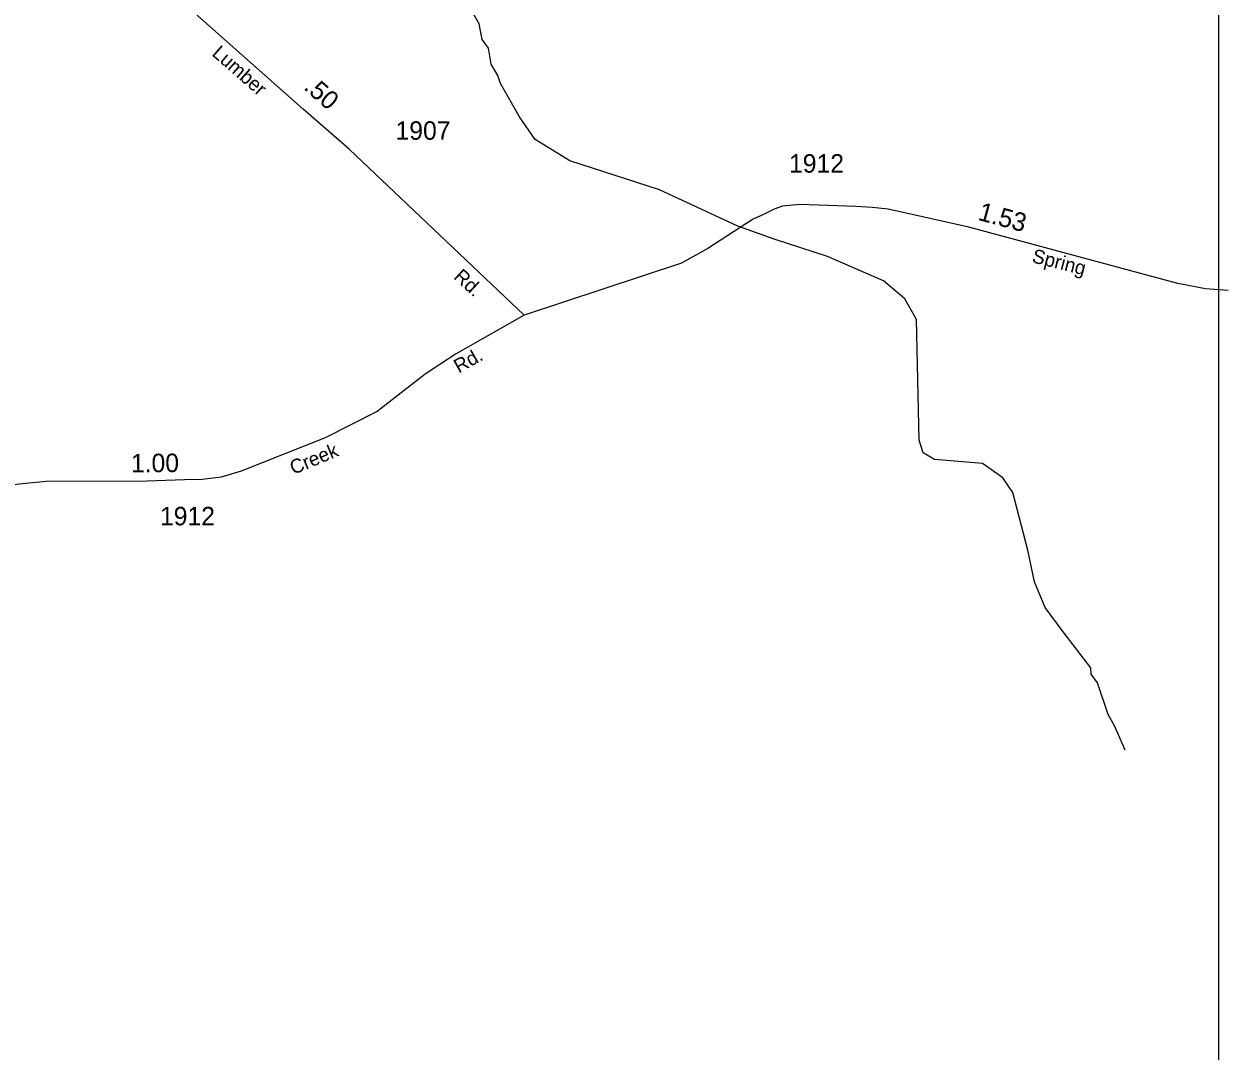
# Model space of a CAD drawing. Extents: x 2532689 to 2764727, y 536648 to 732970.
# Drawn here: x 2687851 to 2695958, y 575256 to 582198 of the extents above; entities that cross this region are included whole.
import ezdxf

# ---------------------------------------------------------------- set-up
doc = ezdxf.new("R2010")
doc.units = 0
for name, color, linetype in [('Exist Hydrographic Creek Single Shore', 7, 'Continuous'), ('Exist Road Secondary Mileage Hundredths English Label', 7, 'Continuous'), ('Exist Road Secondary Type 51 Attributed', 7, 'Continuous'), ('Exist Road Secondary Type 51 Label', 7, 'Continuous'), ('Exist Road Secondary Type 51 Number Label', 7, 'Continuous'), ('Map Preparation Inset Cut Line', 7, 'Continuous')]:
    doc.layers.add(name, color=color, linetype=linetype)

msp = doc.modelspace()

# ---------------------------------------------------------------- linework, layer by layer
at = {"layer": 'Exist Hydrographic Creek Single Shore'}
for points in [[(2692527.2, 580902.1), (2692147.5, 581077.1), (2691542.4, 581272.6), (2691306.3, 581417.4), (2691202.4, 581570.8), (2691072.4, 581795.4), (2691054.3, 581850.5), (2691010.4, 581927.6), (2690991.4, 582035.1), (2690948.5, 582092.5), (2690929.5, 582200.1), (2690868.3, 582306), (2690850.5, 582370.9), (2690753.3, 582593.6)], [(2695295.4, 577290), (2695259.5, 577374), (2695224.5, 577454.7), (2695181.4, 577531.7), (2695109.4, 577745.5), (2695066.4, 577802.9), (2695065.4, 577845.5), (2694876.5, 578090.7), (2694755.5, 578253.3), (2694684.4, 578427.8), (2694638.4, 578642.6), (2694537.3, 579032.5), (2694468.4, 579131.6), (2694332.5, 579227.9), (2694007.5, 579254.2), (2693931.4, 579300.4), (2693904.3, 579384.6), (2693885.5, 580201.4), (2693806.3, 580339.5), (2693662.4, 580461.7), (2693283.5, 580627), (2692922.4, 580743.8), (2692678.3, 580832.5), (2692527.2, 580902.1)]]:
    msp.add_lwpolyline(points, dxfattribs=at)
at = {"layer": 'Exist Road Secondary Type 51 Attributed'}
for points in [[(2691231.8, 580229.9), (2690048.7, 581351.9), (2689738.3, 581622.7), (2688926.2, 582341.6)], [(2695993.4, 580397.4), (2695839.5, 580407.8), (2695653.1, 580443.3), (2694238.6, 580825.8), (2693694.1, 580946.4), (2693587.7, 580958), (2693475.5, 580963.8), (2693096.4, 580977.4), (2692980.4, 580965.8), (2692924.3, 580946.4), (2692854.6, 580913.5), (2692781.1, 580878.7), (2692730.8, 580847.7), (2692475.5, 580681.3), (2692419.4, 580648.4), (2692369.1, 580621.3), (2692297.5, 580582.6), (2691231.8, 580229.9)], [(2691231.8, 580229.9), (2690768, 579967.5), (2690563.5, 579832.1), (2690237.9, 579578.4), (2689887.9, 579401.1), (2689318.9, 579174.8), (2689183.4, 579134.4), (2689056.7, 579120), (2688935.7, 579117.1), (2688685, 579108.5), (2688000.6, 579105.5), (2687819.1, 579087.3), (2687218.8, 578999.4), (2686890.2, 578944.2), (2685991.3, 578805.8)]]:
    msp.add_lwpolyline(points, dxfattribs=at)
at = {"layer": 'Map Preparation Inset Cut Line'}
msp.add_lwpolyline([(2682347.2, 562752.7), (2695930.4, 562752.7), (2695930.4, 589310.3), (2682347.2, 589310.3)], close=True, dxfattribs=at)

# ---------------------------------------------------------------- texts
at = {"layer": 'Exist Road Secondary Mileage Hundredths English Label'}
for s, rotation, p in [('.50', 318.89117, (2689735.7, 581761.4)), ('1.53', 344.86964, (2694295.1, 580875.2)), ('1.00', 0.39927, (2688574.4, 579167.3))]:
    msp.add_text(s, height=125, rotation=rotation, dxfattribs=at).set_placement(p)
at = {"layer": 'Exist Road Secondary Type 51 Label'}
for s, rotation, p in [('Lumber', 318.89117, (2689116, 581990)), ('Spring', 345.83024, (2694661, 580588.4)), ('Rd.', 317.38418, (2690750.5, 580481.7)), ('Rd.', 29.37306, (2690791.1, 579835.1)), ('Creek', 22.63051, (2689672.8, 579150.4))]:
    msp.add_text(s, height=95, rotation=rotation, dxfattribs=at).set_placement(p)
at = {"layer": 'Exist Road Secondary Type 51 Number Label'}
for s, p in [('1907', (2690363.1, 581415.6)), ('1912', (2693023.6, 581193.3)), ('1912', (2688770.5, 578809.4))]:
    msp.add_text(s, height=125, dxfattribs=at).set_placement(p)

doc.saveas('drawing.dxf')
